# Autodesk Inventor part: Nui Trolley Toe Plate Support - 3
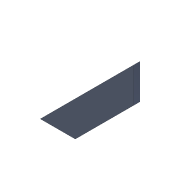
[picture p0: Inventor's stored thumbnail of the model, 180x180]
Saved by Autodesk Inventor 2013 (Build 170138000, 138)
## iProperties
Shininess: 64.0
Length Units: 11269
Angle Units: 11279
Time Units: 11290
Mass Units: 11286
Length Display Precision: 3
Angle Display Precision: 2
Compacted: True
Created: 2002-08
Part Number: Nui Trolley Toe Plate Support - 3
Document SubType Name: Modeling
Designer: kalamea
Density: 1 g/cm^3
Material: Generic
Density: 0.0
Volumn: 0.0
Area: 0.0
PropertySet Name: Model Information
Control State: 0
Master: False
Checked Out: False
DRAWING NUMBER: ME11-2007-PT
d0: 19.050 mm
d2: 101.600 mm
d3: 45.00 deg
d4: 5.080 mm
d5: 0.00 deg
Author: kalamea
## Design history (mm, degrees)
sketch "Sketch1"
  geometry: L1 (0, 0)-(26.941, 0); L2 (26.941, 0)-(71.842, 44.901); L3 (71.842, 44.901)-(71.842, 71.842); L4 (71.842, 71.842)-(0, 0); 1 further point
  constraints: 8 end point, 1 coincident, 1 horizontal, 1 parallel, 1 perpendicular
  dimensions: "d0" = 19.05 distance between parallel lines of L2 L4; "d2" = 101.6 distance of L3.end L1.start; "d3" = 45 deg angle of L2 L1
extrude "Extrusion1" new body sketch "Sketch1" stored distance "d4" = 5.08; taper "d5" = 0 deg
body "Solid1"
